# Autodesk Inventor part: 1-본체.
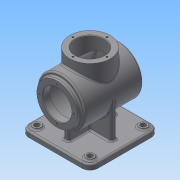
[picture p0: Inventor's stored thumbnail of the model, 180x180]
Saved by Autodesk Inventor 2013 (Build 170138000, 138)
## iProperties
Created: 2015-07
Part Number: 1-본체.
Material: 일반
Document SubType Name: Modeling
Designer: ST1
Density: 1 g/cm^3
Author: ST1
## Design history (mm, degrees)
sketch "스케치1"
  geometry: L1 (0, 0)-(130, 0); L2 (130, 0)-(130, -130); L3 (130, -130)-(0, -130); L4 (0, -130)-(0, 0)
  constraints: 8 end point, 2 parallel, 1 horizontal, 1 perpendicular
  dimensions: "d0" = 130 distance of L1.start L1.end; "d1" = 130 distance of L3.end L1.start
extrude "돌출1" new body sketch "스케치1" distance "d2" = 10; taper "d3" = 0 deg
node "작업 평면1"
sketch "스케치2"
  geometry: L1 (0, 0)-(130, 0) reference; C1 r 45 at (65, 78); 1 further point
  constraints: 1 centre point, 1 midpoint, 1 vertical alignment
  dimensions: "d5" = 78 distance from line of L1 C1.centre; "d6" = 90 diameter of C1
extrude "돌출2" join sketch "스케치2" distance "d7" = 110; taper "d8" = 0 deg
sketch "스케치3"
  geometry: C1 r 45 at (0, 0) reference; C2 r 38 at (0, 0); 1 further point
  constraints: 1 centre point, 1 coincident
  dimensions: "d9" = 76 diameter of C2
extrude "돌출3" join sketch "스케치3" distance "d11" = 7; taper "d12" = 0 deg
sketch "스케치4"
  geometry: C1 r 38 at (0, 0) reference; C2 r 27 at (0, 0); 1 further point
  constraints: 1 centre point, 1 coincident
  dimensions: "d13" = 54 diameter of C2
extrude "돌출4" cut sketch "스케치4" distance "d15" = 14; taper "d16" = 0 deg
sketch "스케치5"
  geometry: C1 r 27 at (0, 0) reference; C2 r 40 at (0, 0); 1 further point
  constraints: 1 centre point, 1 coincident
  dimensions: "d17" = 80 diameter of C2
extrude "돌출5" cut sketch "스케치5" distance "d19" = 96; taper "d20" = 0 deg
node "작업 평면2"
sketch "스케치6"
  geometry: L1 (130, 0)-(0, 0) reference; L2 (110, -10)-(20, -10) reference; C1 r 38 at (65, -65); 1 further point
  constraints: 1 centre point, 1 midpoint, 1 vertical alignment
  dimensions: "d22" = 55 distance from line of L2 C1.centre; "d23" = 76 diameter of C1
extrude "돌출6" join sketch "스케치6" stored distance "d24" = 96; taper "d25" = 0 deg
sketch "스케치7"
  geometry: C1 r 38 at (0, 0) reference; C2 r 27 at (0, 0); 1 further point
  constraints: 1 centre point, 1 coincident
  dimensions: "d26" = 54 diameter of C2
extrude "돌출7" cut sketch "스케치7" stored distance "d28" = 96; taper "d29" = 0 deg
sketch "스케치8" dims "d30" = 64
  geometry: C1 r 27 at (0, 0) reference; C2 r 38 at (0, 0) reference; 3 further points
  constraints: 2 vertical alignment, 1 coincident, 2 other
hole "구멍1" sketch "스케치8" at (0, 32) diameter "d32" = 3.242; stored, may be unused: countersink angle "d36" = 90 deg, drill point angle "d38" = 118 deg; dims "d33" = 8, "d34" = 4, "d35" = 2, "d37" = 10
sketch "스케치9" dims "d42" = 64
  geometry: C1 r 27 at (0, 0) reference; C2 r 38 at (0, 0) reference; 3 further points
  constraints: 2 vertical alignment, 1 coincident, 2 other
hole "구멍2" sketch "스케치9" at (0, 32) diameter "d44" = 3.242; stored, may be unused: countersink angle "d48" = 90 deg, drill point angle "d50" = 118 deg; dims "d45" = 8, "d46" = 4, "d47" = 2, "d49" = 10
fillet "모깎기1" dims "d54" = 3
chamfer "모따기1" distance "d55" = 1; stored, may be unused: second distance "d56" = 2, angle "d57" = 45 deg
fillet "모깎기2" dims "d58" = 15
sketch "스케치10"
  geometry: L1 (0, -15)-(0, -115) reference; L2 (115, 0)-(15, 0) reference; L3 (110, -60)-(110, -70); L4 (20, -70)-(20, -60); L5 (60, -20)-(70, -20); L6 (70, -110)-(60, -110); L7 (20, -60)-(60, -60); L8 (70, -60)-(110, -60); L9 (70, -20)-(70, -60); L10 (70, -70)-(70, -110); L11 (60, -110)-(60, -70); L12 (60, -60)-(60, -20); L13 (110, -70)-(70, -70); L14 (60, -70)-(20, -70); 5 further points
  constraints: 24 end point, 10 parallel, 4 midpoint, 4 perpendicular, 3 horizontal, 3 horizontal alignment, 3 vertical alignment
  dimensions: "d59" = 10 distance of L4.start L4.end; "d61" = 20 distance between parallel lines of L1 L4; "d62" = 90 distance of L3.end L4.start; "d63" = 10 distance of L5.start L5.end; "d64" = 20 distance between parallel lines of L2 L5; "d65" = 90 distance of L6.end L5.start
extrude "돌출8" join sketch "스케치10" stored distance "d66" = 96; taper "d67" = 0 deg
fillet "모깎기3" dims "d68" = 3
fillet "모깎기4" dims "d69" = 3
sketch "스케치11"
  geometry: L1 (0, -15)-(0, -115) reference; L2 (115, 0)-(15, 0) reference; C1 r 7.5 at (15, -15); C2 r 7.5 at (115, -15); C3 r 7.5 at (15, -115); C4 r 7.5 at (115, -115); A1 r 15 centre (15, -15) between (15, 0) and (0, -15) reference; 1 further point
  constraints: 4 centre point, 3 equal radius, 2 horizontal alignment, 2 vertical alignment
  dimensions: "d70" = 15 distance from line of L2 C1.centre; "d71" = 15 distance from line of L1 C1.centre; "d72" = 100 distance of C2.centre A1.centre; "d73" = 100 distance of C3.centre A1.centre; "d74" = 15 diameter of C1
extrude "돌출9" join sketch "스케치11" distance "d75" = 3; taper "d76" = 0 deg
sketch "스케치12"
  geometry: L1 (-100, 15)-(0, 15) reference; L2 (15, 0)-(15, -100) reference; L3 (0, -115)-(-100, -115) reference; L4 (-115, -100)-(-115, 0) reference; C1 r 5 at (-100, 0); C2 r 5 at (0, 0); C3 r 5 at (0, -100); C4 r 5 at (-100, -100); A1 r 15 centre (-100, 0) between (-100, 15) and (-115, 0) reference; A2 r 15 centre (0, 0) between (15, 0) and (0, 15) reference; A3 r 15 centre (0, -100) between (0, -115) and (15, -100) reference; A4 r 15 centre (-100, -100) between (-115, -100) and (-100, -115) reference; 1 further point
  constraints: 4 centre point, 4 coincident, 3 equal radius
  dimensions: "d77" = 10 diameter of C4
extrude "돌출10" cut sketch "스케치12" stored distance "d79" = 3; taper "d80" = 0 deg
fillet "모깎기5" dims "d81" = 3
sketch "스케치13"
  geometry: C1 r 42 at (0, 0) reference; 2 further points
  constraints: 1 coincident, 1 other
feature "엠보싱1" sketch "스케치13" dims "d0" = 130, "d1" = 130, "d82" = 0.5, "d83" = 0
node "솔리드1"
pattern_circular "원형 패턴1" dims angle "d40" = 360 deg
pattern_circular "원형 패턴2" dims angle "d52" = 360 deg
node "투영된 루프1"
